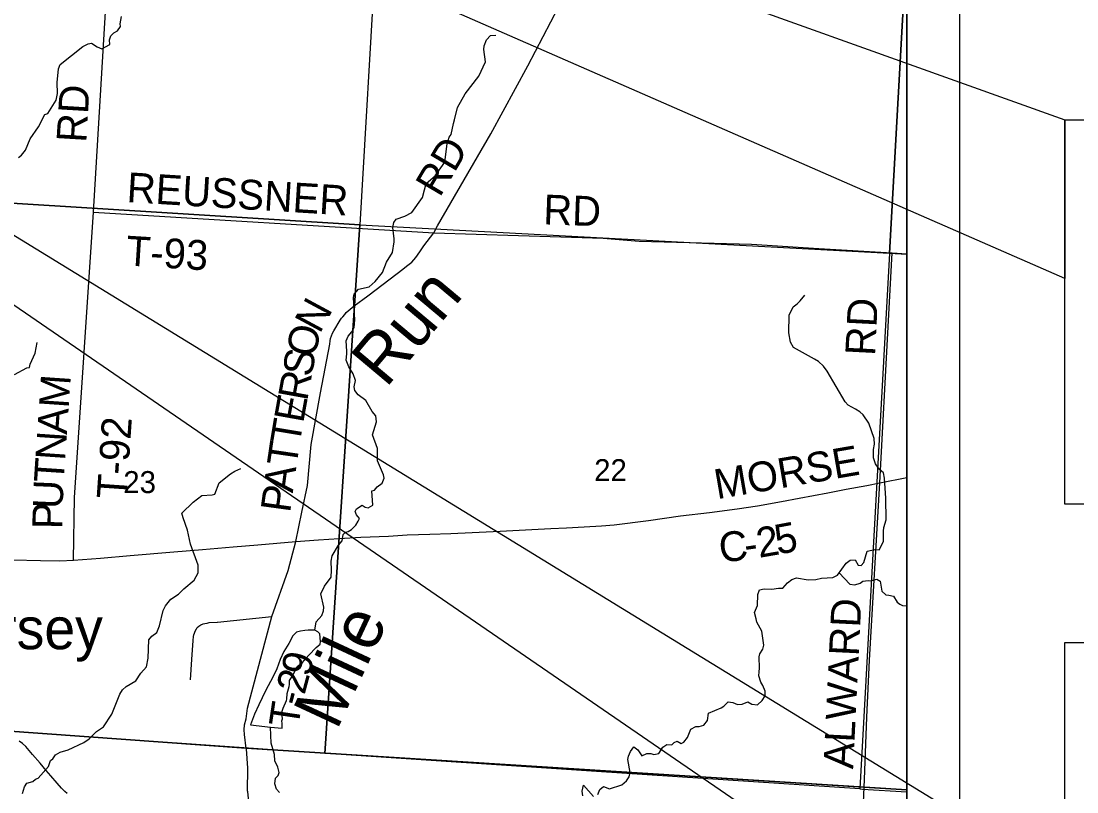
# Model space of a CAD drawing. Extents: x 0 to 91.3, y -0.7 to 22.
# Drawn here: x 7.212 to 9.224, y 15.256 to 16.725 of the extents above; entities that cross this region are included whole.
import ezdxf

# ---------------------------------------------------------------- set-up
doc = ezdxf.new("R2010")
doc.units = 0
for name, color, linetype in [('GM_X_Corporation', 7, 'Continuous'), ('GM_X_County_Road', 7, 'Continuous'), ('GM_X_County_Road_Text', 7, 'Continuous'), ('GM_X_Minor_Lake', 7, 'Continuous'), ('GM_X_Minor_River', 7, 'Continuous'), ('GM_X_Minor_River_Text', 7, 'Continuous'), ('GM_X_Section_Text', 7, 'Continuous'), ('GM_X_Township_Road', 7, 'Continuous'), ('GM_X_Township_Road_Text', 7, 'Continuous'), ('GM_X_Unincorporated_Text', 7, 'Continuous'), ('SH_Data', 7, 'Continuous'), ('SH_Text', 7, 'Continuous')]:
    doc.layers.add(name, color=color, linetype=linetype)

msp = doc.modelspace()

# ---------------------------------------------------------------- linework, layer by layer
at = {"layer": 'GM_X_Corporation'}
for points in [[(4.8242, 18.6326), (4.7833, 18.1361), (4.7799, 18.0944), (4.7688, 17.9561), (4.7562, 17.8002), (4.7391, 17.5254), (4.7381, 17.5094), (4.7369, 17.4842), (4.7039, 16.921), (4.6966, 16.7952), (4.624, 15.5538), (4.6241, 15.5494), (4.6027, 15.2253), (4.5901, 15.0403), (4.5616, 14.5843), (4.5361, 14.2234), (4.5273, 14.1), (8.9, 14.1), (8.9, 20.9)], [(4.8242, 18.6326), (4.7833, 18.1361), (4.7799, 18.0944), (4.7688, 17.9561), (4.7562, 17.8002), (4.7391, 17.5254), (4.7381, 17.5094), (4.7369, 17.4842), (4.7039, 16.921), (4.6966, 16.7952), (4.624, 15.5538), (4.6241, 15.5494), (5.2553, 15.5081), (5.7371, 15.476), (6.438, 15.425), (7.1732, 15.3725), (7.6407, 15.3389), (8.8181, 15.2648), (8.9, 15.2596), (8.9, 20.4953)]]:
    msp.add_lwpolyline(points, dxfattribs=at)
for points in [[(6.9092, 17.4181), (7.9172, 17.3589), (7.8571, 16.3365), (6.8465, 16.3992)], [(8.9, 16.8754), (8.9, 17.3103), (7.9172, 17.3589), (7.8571, 16.3365), (8.8671, 16.2825)], [(8.9, 16.2805), (8.9, 16.8754), (8.8671, 16.2825)], [(6.8465, 16.3992), (7.8571, 16.3365), (7.7907, 15.3289), (7.2092, 15.3695), (6.7835, 15.4003)], [(7.8571, 16.3365), (8.8671, 16.2825), (8.8104, 15.2613), (8.3084, 15.2947), (7.8025, 15.328), (7.7907, 15.3289)], [(8.9, 15.2558), (8.9, 16.2805), (8.8671, 16.2825), (8.8104, 15.2613), (8.8156, 15.2609)], [(4.5273, 14.1), (8.9, 14.1), (8.9, 15.2596), (8.8181, 15.2648), (7.6407, 15.3389), (7.1732, 15.3725), (6.438, 15.425), (5.7371, 15.476), (5.2553, 15.5081), (4.6241, 15.5494), (4.6027, 15.2253), (4.5901, 15.0403), (4.5616, 14.5843), (4.5361, 14.2234)], [(4.5286, 14.1), (8.9, 14.1), (8.9, 15.2593), (7.6407, 15.3389), (7.1732, 15.3725), (5.7332, 15.4763), (5.3098, 15.5058), (4.9415, 15.5315), (4.9055, 15.5345), (4.624, 15.5538)]]:
    msp.add_lwpolyline(points, close=True, dxfattribs=at)
at = {"layer": 'GM_X_County_Road'}
for points in [[(7.1957, 15.6977), (7.2485, 15.6967), (7.2857, 15.696), (7.3114, 15.6975), (7.3628, 15.7013), (7.4198, 15.7062), (7.503, 15.7129), (7.5576, 15.7174), (7.6158, 15.7227), (7.6629, 15.7266), (7.7354, 15.7326), (7.7784, 15.7358), (7.8177, 15.7384), (7.8593, 15.7409), (7.9119, 15.7432), (7.9474, 15.7452), (7.9907, 15.7468), (8.0305, 15.7483), (8.0713, 15.7502), (8.1245, 15.7523), (8.2213, 15.7575), (8.2512, 15.759), (8.2851, 15.7608), (8.3178, 15.7624), (8.3422, 15.7647), (8.4075, 15.773), (8.4683, 15.7818), (8.5239, 15.7882), (8.5767, 15.7952), (8.6152, 15.8011), (8.6609, 15.8089), (8.6945, 15.8153), (8.7491, 15.8256), (8.7839, 15.8325), (8.8234, 15.8396), (8.8484, 15.8444), (8.9, 15.855)], [(7.2993, 15.2524), (7.2948, 15.2566), (7.2887, 15.2628), (7.2804, 15.2723), (7.2684, 15.286), (7.2597, 15.2964), (7.2477, 15.3106), (7.2335, 15.327), (7.2209, 15.3422), (7.2144, 15.3476), (7.2079, 15.352)]]:
    msp.add_lwpolyline(points, dxfattribs=at)
at = {"layer": 'GM_X_Minor_Lake'}
for points in [[(7.7712, 15.5636), (7.7644, 15.564), (7.7587, 15.5641), (7.7522, 15.5633), (7.7443, 15.5619), (7.7363, 15.56), (7.7287, 15.5521), (7.7245, 15.543), (7.7218, 15.5381), (7.7122, 15.5234), (7.7057, 15.5079), (7.6991, 15.4901), (7.6922, 15.4757), (7.6773, 15.4481), (7.665, 15.4213), (7.6562, 15.4039), (7.6491, 15.3832), (7.6868, 15.3791)], [(7.6868, 15.3791), (7.7095, 15.3767), (7.7092, 15.3858), (7.7088, 15.3911), (7.7096, 15.3945), (7.7093, 15.4005), (7.7085, 15.4078), (7.7109, 15.4153), (7.7174, 15.4297), (7.7178, 15.4323), (7.7186, 15.443), (7.7225, 15.4562), (7.7229, 15.4604), (7.7233, 15.468), (7.7271, 15.4736), (7.7321, 15.4823), (7.7378, 15.4948), (7.7481, 15.5019), (7.7546, 15.5099), (7.7603, 15.5159), (7.7741, 15.5306), (7.7817, 15.537), (7.7825, 15.5419), (7.781, 15.5571), (7.7769, 15.5609), (7.7712, 15.5636)]]:
    msp.add_lwpolyline(points, dxfattribs=at)
at = {"layer": 'GM_X_Minor_River'}
for points in [[(7.2068, 16.4649), (7.2122, 16.4691), (7.2198, 16.4789), (7.2286, 16.5004), (7.2447, 16.5231), (7.257, 16.5465), (7.2623, 16.5488), (7.2787, 16.5741), (7.2807, 16.5866), (7.2804, 16.6074), (7.2829, 16.634), (7.2859, 16.6419), (7.329, 16.6765), (7.3396, 16.6814), (7.3457, 16.6825), (7.3563, 16.6756), (7.3657, 16.6718), (7.3809, 16.6804), (7.3798, 16.6891), (7.3829, 16.6967), (7.3886, 16.7024), (7.3955, 16.7065), (7.4012, 16.7144), (7.4005, 16.7193), (7.4028, 16.7337)], [(7.7712, 15.5636), (7.7743, 15.5795), (7.785, 15.592), (7.7881, 15.6007), (7.7885, 15.6075), (7.7826, 15.6329), (7.7899, 15.6477), (7.8029, 15.665), (7.8033, 15.6779), (7.8023, 15.6954), (7.8046, 15.7056), (7.8165, 15.726), (7.8237, 15.7339), (7.8257, 15.746), (7.8299, 15.7509), (7.8348, 15.7517), (7.8413, 15.7558), (7.8493, 15.7637), (7.8543, 15.7717), (7.8569, 15.7766), (7.8509, 15.7838), (7.8483, 15.7899), (7.851, 15.7952), (7.862, 15.8023), (7.8673, 15.7981), (7.8734, 15.7969), (7.8817, 15.8018), (7.88, 15.8295), (7.8849, 15.8306), (7.8903, 15.837), (7.8998, 15.8438), (7.9036, 15.8533), (7.9021, 15.8601), (7.8909, 15.8867), (7.8911, 15.9098), (7.8813, 15.9361), (7.8891, 15.9607), (7.888, 15.9724), (7.8808, 15.9808), (7.8684, 16.0014), (7.8541, 16.0121), (7.8477, 16.0204), (7.8466, 16.0277), (7.8489, 16.0398), (7.8445, 16.0527), (7.8362, 16.066), (7.8313, 16.0782), (7.8322, 16.0907), (7.8326, 16.0956), (7.8315, 16.1153), (7.835, 16.1244), (7.8423, 16.1327), (7.8465, 16.141), (7.8477, 16.1554), (7.8453, 16.1979), (7.8465, 16.204), (7.8545, 16.2138), (7.875, 16.2182), (7.8864, 16.2284), (7.9005, 16.2458), (7.9078, 16.2654), (7.9197, 16.2836), (7.9228, 16.304), (7.9229, 16.3097), (7.92, 16.3313), (7.9219, 16.3408), (7.9265, 16.3469), (7.9432, 16.3528), (7.9565, 16.3599), (7.9768, 16.3883), (7.9806, 16.4034), (7.9834, 16.4155), (8.0009, 16.4295), (8.0192, 16.4559), (8.024, 16.4911), (8.0275, 16.5036), (8.0313, 16.5085), (8.0356, 16.5297), (8.0375, 16.5365), (8.0433, 16.56), (8.0579, 16.5861), (8.0838, 16.6197), (8.0965, 16.6469), (8.0936, 16.6708), (8.0944, 16.6773), (8.0986, 16.689), (8.1063, 16.6973), (8.1165, 16.698)], [(8.6251, 15.5278), (8.6275, 15.5354), (8.6234, 15.5616), (8.6141, 15.5791), (8.6126, 15.5851), (8.6096, 15.5973), (8.6154, 15.6105), (8.6159, 15.6317), (8.619, 15.6408), (8.6277, 15.6427), (8.6425, 15.6418), (8.655, 15.644), (8.6633, 15.6436), (8.6725, 15.6538), (8.6805, 15.6602), (8.6896, 15.6635), (8.7119, 15.6596), (8.7263, 15.6603), (8.737, 15.6629), (8.759, 15.6639), (8.7677, 15.6684), (8.7841, 15.6918), (8.7921, 15.6971), (8.8012, 15.6981), (8.8073, 15.6875), (8.8129, 15.6871), (8.8179, 15.6927), (8.8241, 15.7143), (8.8389, 15.7176), (8.8472, 15.7168), (8.8553, 15.7327), (8.8554, 15.7528), (8.8558, 15.7596), (8.8604, 15.7744), (8.8595, 15.8157), (8.8571, 15.8536), (8.8553, 15.8635), (8.847, 15.8708), (8.8398, 15.881), (8.8361, 15.8924), (8.8362, 15.9084), (8.8381, 15.9186), (8.8374, 15.9292), (8.8273, 15.9581), (8.8164, 15.9741), (8.81, 15.9798), (8.8017, 15.9848), (8.7881, 15.9925), (8.7821, 15.9993), (8.7483, 16.0575), (8.7411, 16.0667), (8.7313, 16.0758), (8.7238, 16.0804), (8.6841, 16.1027), (8.6781, 16.1129), (8.6752, 16.1304), (8.6753, 16.1642), (8.683, 16.18), (8.691, 16.1861), (8.6964, 16.1917), (8.7051, 16.2023)], [(7.1988, 16.0509), (7.2224, 16.0636), (7.2277, 16.0647), (7.2289, 16.0708), (7.2385, 16.092), (7.242, 16.112)], [(7.2141, 15.2526), (7.2183, 15.2654), (7.2225, 15.2722), (7.2339, 15.2752), (7.2389, 15.2797), (7.2442, 15.2816), (7.2636, 15.3039), (7.2675, 15.3152), (7.2724, 15.3186), (7.2774, 15.3261), (7.2858, 15.331), (7.301, 15.3355), (7.331, 15.3497), (7.3413, 15.3565), (7.3554, 15.3704), (7.3687, 15.3798), (7.3848, 15.4036), (7.4001, 15.4418), (7.4047, 15.4498), (7.4116, 15.4565), (7.4306, 15.4674), (7.4398, 15.4818), (7.4508, 15.4942), (7.454, 15.5105), (7.4549, 15.5454), (7.461, 15.5526), (7.4702, 15.5593), (7.4752, 15.5718), (7.4825, 15.601), (7.4868, 15.6104), (7.4971, 15.6229), (7.5119, 15.6323), (7.5218, 15.6424), (7.5416, 15.6594), (7.5489, 15.6734), (7.549, 15.6878), (7.5344, 15.7277), (7.5289, 15.7546), (7.5207, 15.7778), (7.5181, 15.7865), (7.5398, 15.8077), (7.5558, 15.8205), (7.5759, 15.8215), (7.5808, 15.8233), (7.5893, 15.8445), (7.611, 15.8615), (7.619, 15.8667), (7.6304, 15.872)], [(8.7709, 15.6729), (8.7915, 15.6512), (8.8006, 15.6504), (8.8109, 15.6537), (8.8162, 15.6571), (8.826, 15.6586), (8.831, 15.6578), (8.8427, 15.6607), (8.8492, 15.6573), (8.8521, 15.6379), (8.8596, 15.631), (8.8657, 15.6306), (8.8744, 15.6287), (8.8815, 15.6173), (8.8864, 15.6131), (8.8917, 15.6111), (8.9, 15.6103)], [(8.3108, 15.2506), (8.3147, 15.2604), (8.3215, 15.2657), (8.3329, 15.2615), (8.3564, 15.2693), (8.3652, 15.2764), (8.3709, 15.284), (8.3725, 15.2927), (8.3681, 15.3174), (8.3692, 15.3234), (8.3731, 15.3325), (8.3792, 15.3412), (8.3871, 15.3355), (8.395, 15.324), (8.4041, 15.3285), (8.4117, 15.3285), (8.4174, 15.3266), (8.4273, 15.3284), (8.4345, 15.3405), (8.4425, 15.3458), (8.4516, 15.3453), (8.4566, 15.3495), (8.4619, 15.3525), (8.4695, 15.3475), (8.4748, 15.3501), (8.4817, 15.3595), (8.4882, 15.3751), (8.4977, 15.3803), (8.5041, 15.3803), (8.5129, 15.3825), (8.5197, 15.3919), (8.5217, 15.4059), (8.5457, 15.416), (8.551, 15.4187), (8.5594, 15.427), (8.5681, 15.4261), (8.5772, 15.4223), (8.5859, 15.4226), (8.5965, 15.4271), (8.6045, 15.4229), (8.6151, 15.4217), (8.6238, 15.4296), (8.6296, 15.4387), (8.6296, 15.4474), (8.6255, 15.4584), (8.6214, 15.4649), (8.6177, 15.477), (8.6181, 15.4842), (8.6192, 15.4911), (8.6186, 15.5127), (8.6198, 15.5184), (8.6251, 15.5278)], [(7.7043, 15.2542), (7.6982, 15.2607), (7.6953, 15.271), (7.6965, 15.2816), (7.7014, 15.2868), (7.7033, 15.2925), (7.7007, 15.3024), (7.6951, 15.3146), (7.6948, 15.3267), (7.6881, 15.3483), (7.6868, 15.3791)], [(8.2824, 15.2481), (8.2809, 15.2572), (8.2836, 15.2682), (8.3028, 15.2465)]]:
    msp.add_lwpolyline(points, dxfattribs=at)
at = {"layer": 'GM_X_Township_Road'}
for points in [[(7.3114, 15.6975), (7.3131, 15.8164), (7.3495, 16.3603), (7.4112, 17.39)], [(7.7354, 15.7326), (7.7466, 15.7887), (7.7574, 15.8395), (7.7643, 15.9177), (7.7825, 16.0162), (7.8, 16.109), (7.8004, 16.1151), (7.8011, 16.1197), (7.8033, 16.1246), (7.8052, 16.1299), (7.8074, 16.1345), (7.8198, 16.1544), (7.8221, 16.1585), (7.8247, 16.1612), (7.8285, 16.1658), (7.8315, 16.1693), (7.8466, 16.1819), (7.8727, 16.2011), (7.9153, 16.2337), (7.9395, 16.2517), (7.9463, 16.2575), (7.9561, 16.2651), (7.964, 16.2739), (7.9719, 16.285), (7.9794, 16.2965), (7.9986, 16.3213), (8.005, 16.3346), (8.107, 16.5097), (8.1774, 16.6397), (8.2507, 16.78)], [(7.3495, 16.3603), (7.9986, 16.3213), (8.3213, 16.3112), (8.3895, 16.3053), (8.6039, 16.2997), (8.7321, 16.291), (8.8716, 16.2828), (8.9, 16.2811)], [(8.8484, 15.8444), (8.864, 16.1422), (8.8716, 16.2828)], [(8.8189, 15.2791), (8.8237, 15.3977), (8.8287, 15.5065), (8.8484, 15.8444)], [(7.641, 15.3374), (7.6409, 15.3384), (7.6374, 15.3648), (7.6365, 15.3736), (7.6374, 15.3836), (7.6403, 15.3951), (7.6429, 15.4149), (7.6894, 15.5899), (7.7209, 15.6777), (7.7354, 15.7326)], [(7.5342, 15.4691), (7.5373, 15.5078), (7.5393, 15.5439), (7.54, 15.5515), (7.5411, 15.5549), (7.5418, 15.558), (7.5433, 15.5622), (7.5459, 15.5664), (7.5471, 15.569), (7.5501, 15.5717), (7.5539, 15.574), (7.5584, 15.5756), (7.5615, 15.5763), (7.5664, 15.5772), (7.5698, 15.5783), (7.5853, 15.5788)], [(7.5853, 15.5788), (7.5861, 15.5788), (7.6894, 15.5899)], [(7.6762, 14.931), (7.6742, 14.9379), (7.6719, 14.9435), (7.6712, 14.9479), (7.6679, 14.9886), (7.667, 15.0056), (7.6526, 15.1549), (7.6518, 15.1712), (7.6497, 15.1966), (7.6435, 15.2562), (7.6434, 15.2572), (7.6439, 15.3006), (7.641, 15.3374)], [(8.7578, 14.1), (8.7914, 14.7233), (8.8057, 14.9979), (8.8139, 15.1608), (8.8183, 15.2643), (8.8189, 15.2791)]]:
    msp.add_lwpolyline(points, dxfattribs=at)
at = {"layer": 'SH_Data'}
for p, q in [((9, 21), (9, 14)), ((8.9, 20.9), (8.9, 14.1))]:
    msp.add_line(p, q, dxfattribs=at)
at = {"layer": 'SH_Text'}
for points in [[(9.2012, 16.2343), (5.4038, 17.8952), (9.2012, 16.5366)], [(9.2012, 14.8079), (5.3743, 17.4358), (9.2012, 15.0876)], [(9.2012, 16.5366), (11.1395, 16.5366), (11.1395, 15.8041), (9.2012, 15.8041)], [(9.2012, 15.5404), (11.1395, 15.5404), (11.1395, 14.8079), (9.2012, 14.8079)]]:
    msp.add_lwpolyline(points, close=True, dxfattribs=at)

# ---------------------------------------------------------------- texts
at = {"layer": 'GM_X_County_Road_Text'}
for s, height, rotation, p in [('MORSE', 0.05682, 9.8001, (8.538, 15.8132)), ('2', 0.0568, 9.8157, (8.6182, 15.7015)), ('5', 0.0568, 10.6246, (8.6535, 15.7076)), ('C', 0.0568, 6.0648, (8.5446, 15.6926)), ('-', 0.0568, 8.1957, (8.5933, 15.6979))]:
    msp.add_text(s, height=height, rotation=rotation, dxfattribs=at).set_placement(p)
at = {"layer": 'GM_X_Minor_River_Text'}
for s, rotation, p in [('Run', 50.0054, (7.907, 16.0238)), ('Mile', 65.0031, (7.8134, 15.3712))]:
    msp.add_text(s, height=0.0947, rotation=rotation, dxfattribs=at).set_placement(p)
at = {"layer": 'GM_X_Section_Text'}
for s, p in [('22', (8.3039, 15.8479)), ('23', (7.4064, 15.8251))]:
    msp.add_text(s, height=0.04186, rotation=0, dxfattribs=at).set_placement(p)
at = {"layer": 'GM_X_Township_Road_Text'}
for s, height, rotation, p in [('RD', 0.05682, 86.5467, (7.3357, 16.4922)), ('RD', 0.05682, 59.4591, (8.0096, 16.3872)), ('REUSSNER', 0.05682, 356.4991, (7.4119, 16.3799)), ('RD', 0.05682, 358.0242, (8.2063, 16.3374)), ('T-93', 0.05682, 356.4464, (7.4103, 16.2591)), ('N', 0.0568, 61.6948, (7.7808, 16.1272)), ('RD', 0.05682, 87.0631, (8.8391, 16.0859)), ('O', 0.0568, 78.0342, (7.7719, 16.0822)), ('S', 0.0568, 79.6909, (7.7651, 16.045)), ('M', 0.0568, 86.0892, (7.3022, 15.9858)), ('R', 0.0568, 79.715, (7.7568, 15.9991)), ('E', 0.0568, 79.7634, (7.7492, 15.9572)), ('A', 0.0568, 86.0928, (7.2988, 15.9359)), ('T-92', 0.05682, 86.1163, (7.4123, 15.8125)), ('T', 0.0568, 80.5504, (7.7423, 15.9155)), ('N', 0.0568, 86.0846, (7.2954, 15.886)), ('T', 0.0568, 81.6566, (7.7362, 15.8738)), ('T', 0.0568, 86.2518, (7.2926, 15.8437)), ('A', 0.0568, 82.2058, (7.7294, 15.8244)), ('U', 0.0568, 87.5549, (7.2905, 15.7941)), ('P', 0.0568, 82.2173, (7.7242, 15.7864)), ('P', 0.0568, 89.0497, (7.2898, 15.7561)), ('ALWARD', 0.05682, 87.1766, (8.7974, 15.2984)), ('9', 0.0568, 74.9439, (7.7608, 15.473)), ('2', 0.0568, 74.9704, (7.7517, 15.4392)), ('-', 0.0568, 75.0872, (7.7457, 15.4167)), ('T', 0.0568, 81.522, (7.7398, 15.3763))]:
    msp.add_text(s, height=height, rotation=rotation, dxfattribs=at).set_placement(p)
at = {"layer": 'GM_X_Unincorporated_Text'}
msp.add_text('Jersey', height=0.07898, rotation=0, dxfattribs=at).set_placement((7.0564, 15.5275))

doc.saveas('drawing.dxf')
